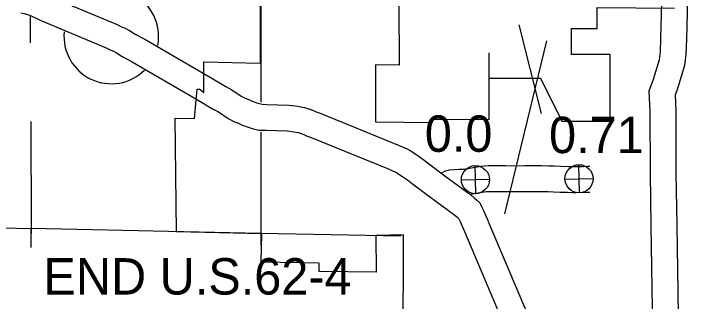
# Model space of a CAD drawing. Extents: x 77230 to 630905, y 790554 to 1662844.
# Drawn here: x 406748 to 422516, y 1593468 to 1600152 of the extents above; entities that cross this region are included whole.
import ezdxf

# ---------------------------------------------------------------- set-up
doc = ezdxf.new("R2010")
doc.units = 0
for name, color, linetype in [('Level 12', 7, 'Continuous'), ('Level 15', 7, 'Continuous'), ('Level 16', 7, 'Continuous'), ('Level 22', 7, 'Continuous'), ('Level 23', 7, 'Continuous'), ('Level 25', 7, 'Continuous'), ('Level 26', 7, 'Continuous'), ('Level 31', 7, 'Continuous'), ('Level 34', 7, 'Continuous')]:
    doc.layers.add(name, color=color, linetype=linetype)

msp = doc.modelspace()

# ---------------------------------------------------------------- linework, layer by layer
at = {"layer": 'Level 12'}
for points in [[(410502, 1597725), (410952, 1597712), (411015, 1598397), (411077, 1598397), (411164, 1598320), (411165, 1599030), (412485, 1598999), (412483, 1600643), (412557, 1600655), (412923, 1600810), (412993, 1600831), (413083, 1600841), (413716, 1600856), (413833, 1600854), (413830, 1600443), (413844, 1600430), (413886, 1600417), (415700, 1600368), (415704, 1598958), (415153, 1598960), (415157, 1597640), (416477, 1597620), (416476, 1597703), (417796, 1597693)], [(420607, 1597653), (420607, 1599203), (419707, 1599203), (419707, 1599803), (420307, 1599803), (420307, 1600290), (422099, 1600279)], [(417796, 1597693), (417794, 1598653), (418985, 1598653), (419485, 1597653)], [(417812, 1592353), (415794, 1592372), (415804, 1595014), (415164, 1594999), (415167, 1594144), (413847, 1594161), (413846, 1594358), (412502, 1594378), (412512, 1595038), (410531, 1595084), (410502, 1597725)], [(419485, 1597653), (420607, 1597653)]]:
    msp.add_lwpolyline(points, dxfattribs=at)
at = {"layer": 'Level 15'}
msp.add_lwpolyline([(417784, 1599237), (417787, 1598021)], dxfattribs=at)
at = {"layer": 'Level 16'}
for points in [[(412305, 1616353), (412330, 1611079), (412357, 1605774), (412491, 1600404), (412491, 1598098)], [(407134, 1600094), (407137, 1599472)], [(407147, 1597647), (407160, 1595171), (407156, 1595043)], [(412491, 1597396), (412491, 1595106)], [(404810, 1595219), (407147, 1595163)], [(415750, 1594986), (412485, 1595043), (407147, 1595163)], [(407147, 1595163), (407151, 1594721)], [(412491, 1595106), (412491, 1594771)]]:
    msp.add_lwpolyline(points, dxfattribs=at)
at = {"layer": 'Level 22'}
for points in [[(421821, 1601271), (421777, 1599575), (421766, 1599264), (421740, 1599079), (421603, 1598625), (421507, 1598349), (421530, 1597875), (421531, 1596446), (421552, 1595225)], [(422417, 1601109), (422377, 1599557), (422365, 1599211), (422328, 1598950), (422174, 1598439), (422112, 1598261), (422130, 1597890), (422131, 1596451), (422152, 1595235)], [(421552, 1595226), (421581, 1593309), (421583, 1593073)], [(422152, 1595235), (422183, 1593161)]]:
    msp.add_lwpolyline(points, dxfattribs=at)
at = {"layer": 'Level 23'}
for points in [[(407604, 1600550), (409155, 1599899), (409252, 1599848), (409321, 1599822), (409440, 1599757), (409571, 1599677), (409795, 1599555), (411336, 1598657), (411664, 1598465), (411816, 1598381), (412036, 1598236), (412130, 1598186), (412212, 1598154), (412289, 1598117), (412422, 1598071), (412488, 1598053), (412522, 1598045), (412627, 1598044), (413139, 1598025), (413230, 1598016), (413289, 1598009), (413352, 1598000), (413413, 1597989), (413502, 1597974), (413609, 1597939), (413711, 1597899), (413776, 1597872), (413872, 1597840), (415702, 1597090), (415799, 1597048), (415890, 1597010), (415960, 1596971), (416114, 1596870), (416254, 1596774), (416383, 1596670), (416767, 1596383)], [(406920, 1600166), (406992, 1600151), (407039, 1600139), (407123, 1600112), (407362, 1600001), (408901, 1599355), (409004, 1599301), (409068, 1599276), (409141, 1599237), (409271, 1599157), (409500, 1599032), (411034, 1598139), (411368, 1597943), (411505, 1597868), (411731, 1597718), (411881, 1597640), (411972, 1597604), (412059, 1597562), (412247, 1597497), (412345, 1597470), (412452, 1597446), (412612, 1597444), (413098, 1597426), (413167, 1597419), (413212, 1597414), (413257, 1597408), (413309, 1597398), (413356, 1597390), (413406, 1597374), (413488, 1597342), (413567, 1597309), (413664, 1597277), (415469, 1596537), (415564, 1596496), (415626, 1596470), (415648, 1596458), (415779, 1596371), (415896, 1596291), (416016, 1596195), (416407, 1595903)], [(416680, 1596448), (416765, 1596494), (416867, 1596522), (417087, 1596538), (417157, 1596538), (417204, 1596541), (417245, 1596545), (417310, 1596555), (417425, 1596576), (417516, 1596595), (417602, 1596610), (417685, 1596619), (417774, 1596623), (417974, 1596623), (418171, 1596621), (418319, 1596619), (418620, 1596622), (418743, 1596624), (418883, 1596623), (419011, 1596623), (419184, 1596617), (419307, 1596613), (419461, 1596608), (419632, 1596601), (419745, 1596599), (419800, 1596599), (419932, 1596603), (419980, 1596604), (420074, 1596607), (420129, 1596607)], [(416764, 1596385), (417366, 1595944), (417450, 1595876), (417499, 1595825), (417578, 1595758), (417627, 1595654), (417665, 1595582), (417774, 1595329)], [(417353, 1595954), (417409, 1595963), (417540, 1595987), (417629, 1596005), (417688, 1596016), (417730, 1596021), (417786, 1596023), (417972, 1596023), (418163, 1596021), (418317, 1596019), (418629, 1596022), (418746, 1596024), (418880, 1596023), (419000, 1596023), (419164, 1596017), (419288, 1596013), (419440, 1596009), (419612, 1596002), (419738, 1595999), (419809, 1595999), (419950, 1596003), (419999, 1596005), (420084, 1596007), (420129, 1596007)], [(416410, 1595901), (417000, 1595468), (417044, 1595432), (417088, 1595387), (417090, 1595386), (417124, 1595322), (417223, 1595091)], [(417775, 1595327), (418784, 1592936), (418826, 1592843), (418853, 1592803), (418888, 1592739), (418911, 1592702), (418916, 1592695), (418937, 1592674), (418957, 1592656), (418983, 1592636), (418991, 1592632), (421296, 1592635), (421357, 1592622), (421411, 1592614), (421442, 1592606), (421514, 1592596), (421592, 1592561), (421706, 1592491), (421777, 1592372), (421818, 1592297), (421863, 1592215), (421896, 1592146), (422516, 1590790)], [(417222, 1595093), (418234, 1592696), (418300, 1592549), (418341, 1592489), (418370, 1592437), (418411, 1592369), (418458, 1592304), (418525, 1592237), (418577, 1592191), (418646, 1592139), (418719, 1592094), (418841, 1592038), (418935, 1592031), (421234, 1592035), (421248, 1592032), (421282, 1592027), (421292, 1592009), (421330, 1591939), (421353, 1591891), (421970, 1590541)]]:
    msp.add_lwpolyline(points, dxfattribs=at)
at = {"layer": 'Level 25'}
for p, q in [((418485, 1599893), (419001, 1597830)), ((419128, 1599517), (418154, 1595506))]:
    msp.add_line(p, q, dxfattribs=at)
at = {"layer": 'Level 26'}
for start, end in [(348.8962, 138.6678), (174.3907, 314.6303)]:
    msp.add_arc((409018, 1599623), 1100, start, end, dxfattribs=at)
at = {"layer": 'Level 34'}
for p, q in [((419890, 1595991), (419875, 1596642)), ((417482, 1595971), (417467, 1596622)), ((419557, 1596309), (420208, 1596324)), ((417149, 1596289), (417800, 1596304))]:
    msp.add_line(p, q, dxfattribs=at)
for centre in [(419882, 1596317), (417475, 1596296)]:
    msp.add_circle(centre, 326, dxfattribs=at)

# ---------------------------------------------------------------- texts
at = {"layer": 'Level 31'}
for s, p in [('0.0', (416300, 1596942)), ('0.71', (419186, 1596911)), ('END U.S.62-4', (407442, 1593628))]:
    msp.add_text(s, height=844.8, dxfattribs=at).set_placement(p)

doc.saveas('drawing.dxf')
